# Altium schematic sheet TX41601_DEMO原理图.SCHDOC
size A3
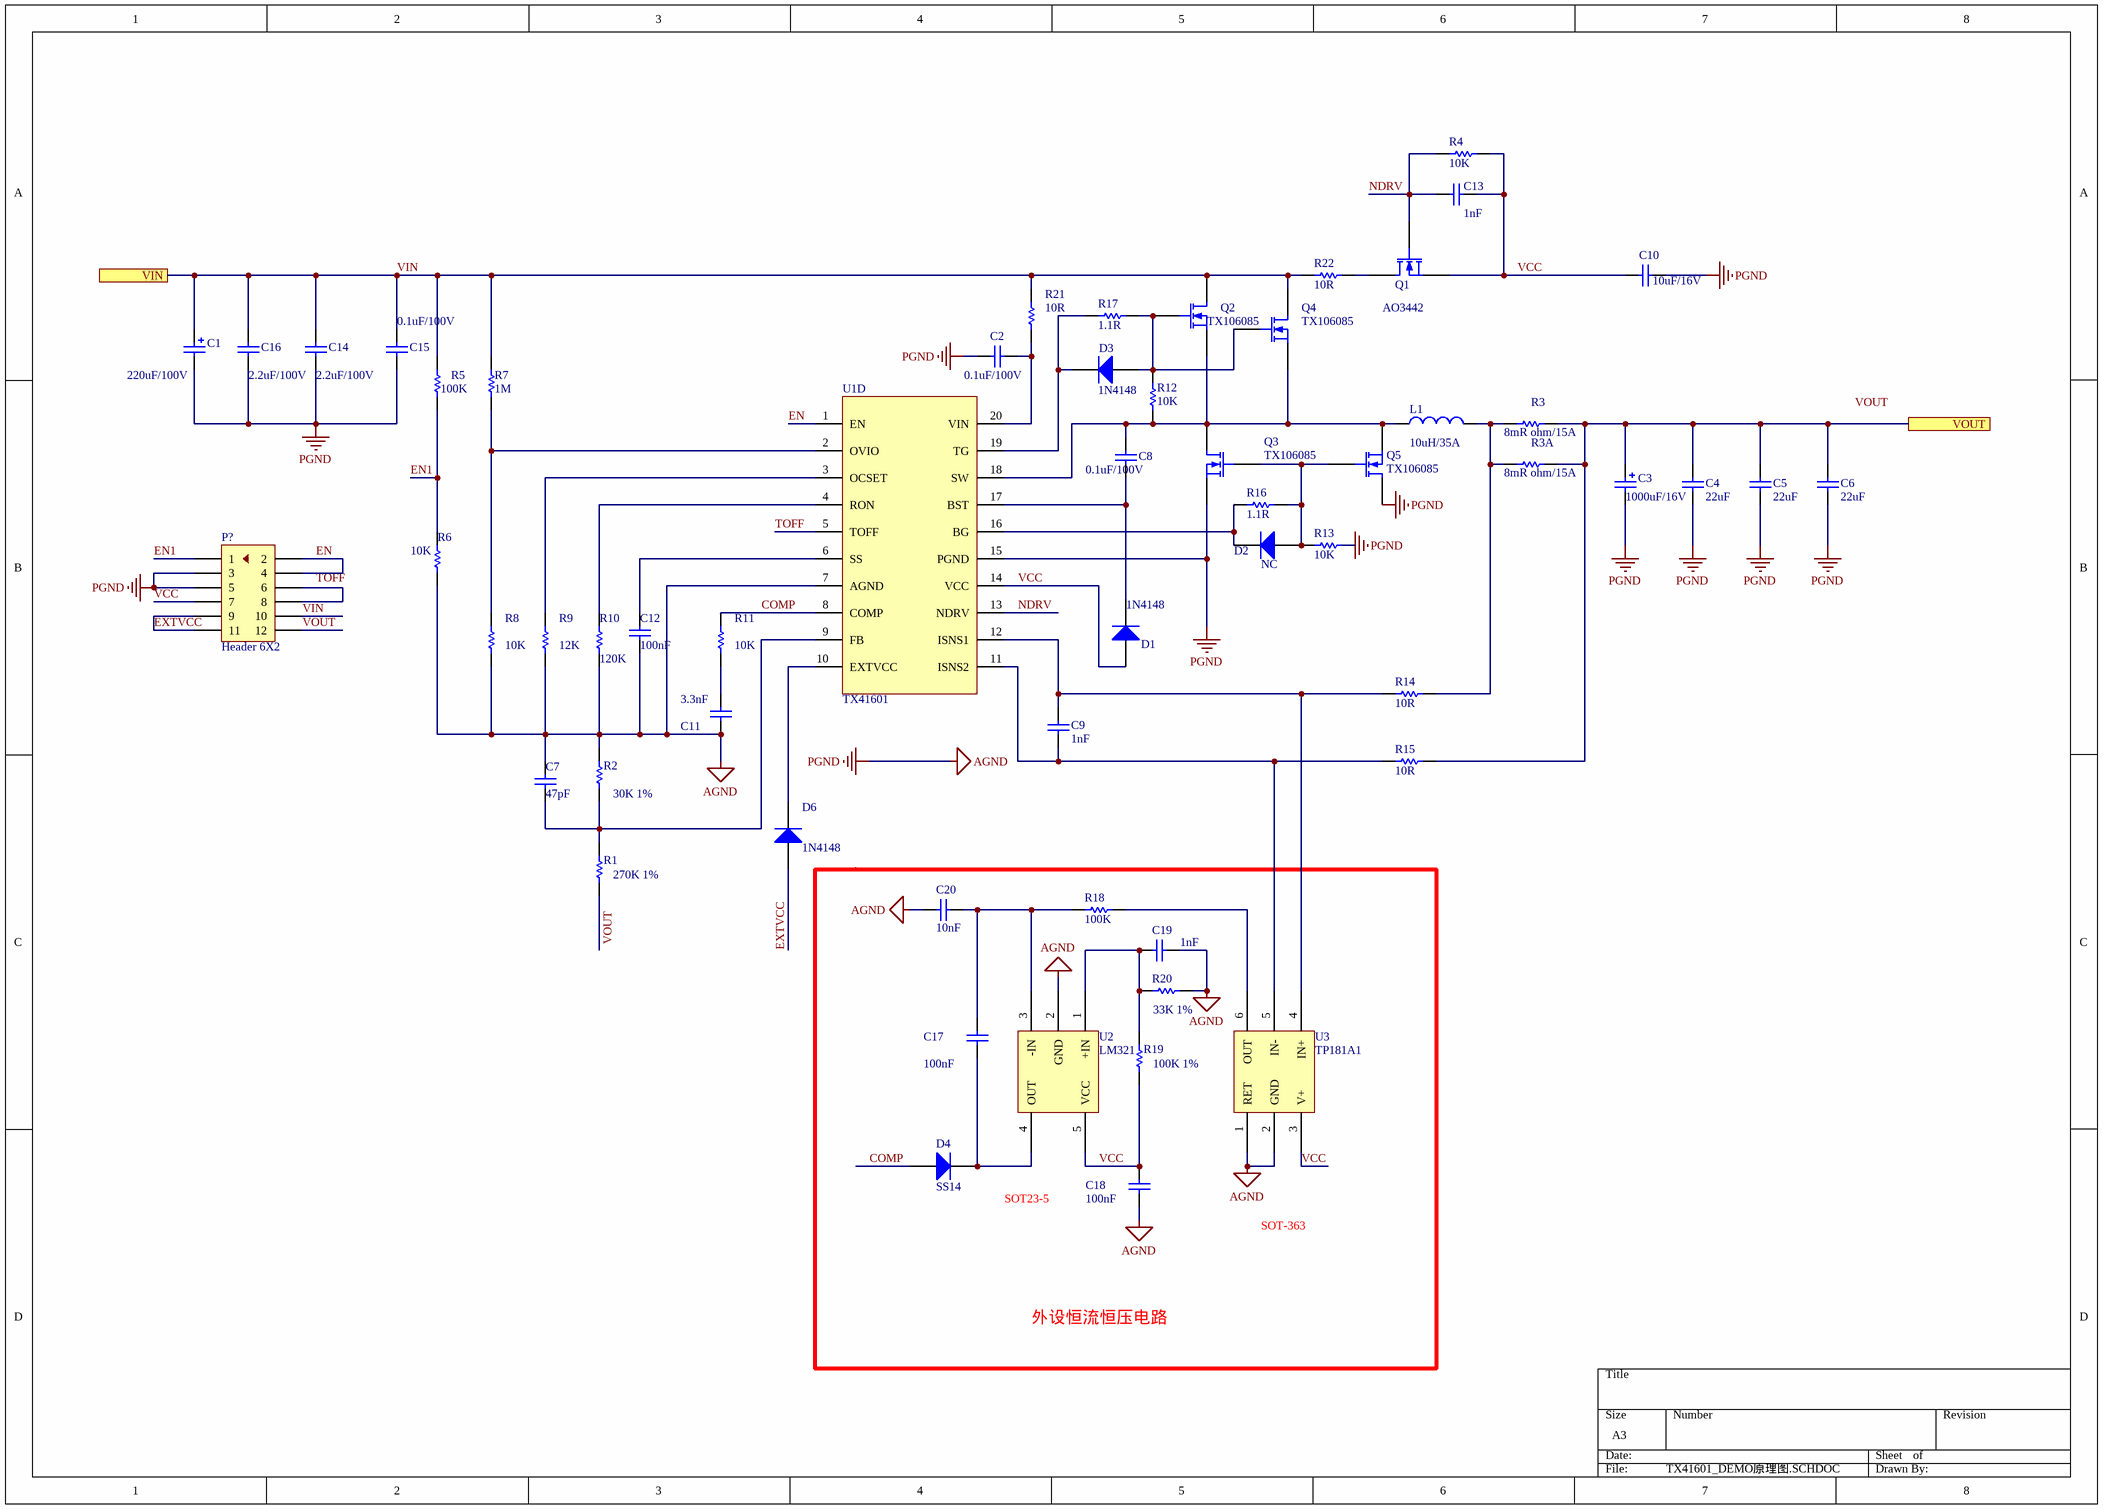
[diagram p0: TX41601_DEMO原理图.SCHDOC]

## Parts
C1  value 220uF/100V  [C13]  (hidden comment: Cap Pol1)
C2  value 0.1uF/100V  [0805]  (hidden comment: Cap Semi)
C3  value 1000uF/16V  [C8]  (hidden comment: Cap Pol1)
C4  value 22uF  [1206]  (hidden comment: Cap Semi)
C5  value 22uF  [1206]  (hidden comment: Cap Semi)
C6  value 22uF  [1206]  (hidden comment: Cap Semi)
C7  value 47pF  [0603]  (hidden comment: Cap Semi)
C8  value 0.1uF/100V  [0603]  (hidden comment: Cap Semi)
C9  value 1nF  [0603]  (hidden comment: Cap Semi)
C10  value 10uF/16V  [0603]  (hidden comment: Cap Semi)
C11  value 3.3nF  [0603]  (hidden comment: Cap Semi)
C12  value 100nF  [0603]  (hidden comment: Cap Semi)
C13  value 1nF  [0603]  (hidden comment: Cap Semi)
C14  value 2.2uF/100V  [1812]  (hidden comment: Cap Semi)
C15  value 0.1uF/100V  [0805]  (hidden comment: Cap Semi)
C16  value 2.2uF/100V  [1812]  (hidden comment: Cap Semi)
C17  value 100nF  [0603]  (hidden comment: Cap Semi)
C18  value 100nF  [0603]  (hidden comment: Cap Semi)
C19  value 1nF  [0603]  (hidden comment: Cap Semi)
C20  value 10nF  [0603]  (hidden comment: Cap Semi)
D1  SubClass: 1N4148  [SMA]  (hidden comment: Diode)
D2  NC  [SMA]
D3  1N4148  [SMA]
D4  SS14  [SMA]
D6  1N4148  [SMA]
L1  10uH/35A  [LIN12]
P?  Header 6X2  [HDR5X2-2.54]
Q1  AO3442  [TO252 - duplicate]
Q2  TX106085  [TO252 - duplicate]
Q3  TX106085  [TO252 - duplicate]
Q4  TX106085  [TO252 - duplicate]
Q5  TX106085  [TO252 - duplicate]
R1  value 30K 1%  [0603]  (hidden comment: Res Semi)
R2  value 270K 1%  [0603]  (hidden comment: Res Semi)
R3  value 8mR ohm/15A  [1812]  (hidden comment: Res Semi)
R3A  value 8mR ohm/15A  [1812]  (hidden comment: Res Semi)
R4  value 10K  [0603]  (hidden comment: Res Semi)
R5  value 100K  [0603]  (hidden comment: Res Semi)
R6  value 10K  [0603]  (hidden comment: Res Semi)
R7  value 1M  [0603]  (hidden comment: Res Semi)
R8  value 10K  [0603]  (hidden comment: Res Semi)
R9  value 12K  [0603]  (hidden comment: Res Semi)
R10  value 120K  [0603]  (hidden comment: Res Semi)
R11  value 10K  [0603]  (hidden comment: Res Semi)
R12  value 10K  [0603]  (hidden comment: Res Semi)
R13  value 10K  [0603]  (hidden comment: Res Semi)
R14  value 10R  [0603]  (hidden comment: Res Semi)
R15  value 10R  [0603]  (hidden comment: Res Semi)
R16  value 1.1R  [0603]  (hidden comment: Res Semi)
R17  value 1.1R  [0603]  (hidden comment: Res Semi)
R18  value 100K  [0603]  (hidden comment: Res Semi)
R19  value 100K 1%  [0603]  (hidden comment: Res Semi)
R20  value 33K 1%  [0603]  (hidden comment: Res Semi)
R21  value 10R  [0603]  (hidden comment: Res Semi)
R22  value 10R  [0603]  (hidden comment: Res Semi)
U1  TX41601  (part D of 4)
U2  LM321
U3  TP181A1

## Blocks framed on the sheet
外设恒流恒压电路: C17-C20 D4 R18-R20 U2 U3

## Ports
VIN, VOUT

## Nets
AGND: C1.2 C2.2 C3.2 C4.1 C5.1 C6.1 C7.2 C10.1 C11.2 C12.1 C14.2 C15.2 C16.2 C18.2 C19.2 C20.1 P?.3 P?.5 Q3.3(S) Q5.1(D) R2.1 R6.1 R8.1 R9.2 R10.2 R13.2 R20.2 U1.7(AGND) U1.15(PGND) U2.2(GND) U3.1(RET) U3.2(GND)  [also labelled PGND]
COMP: D4.1(A) R11.1 U1.8(COMP)
EN: P?.2 P?.4 U1.1(EN)
EN1: P?.1 R5.1 R6.2
EXTVCC: D6.1(A) P?.9 P?.10(11)
NDRV: C13.2 Q1.2(G) R4.2 U1.13(NDRV)
TOFF: U1.5(TOFF)
VCC: C10.2 C13.1 C18.1 D1.1(A) P?.7 Q1.3(S) R4.1 R19.1 U1.14(VCC) U2.5(VCC) U3.3(V+)
VIN: C1.1 C14.1 C15.1 C16.1 P?.10 Q2.1(D) Q4.1(D) R5.2 R7.2 R21.2 R22.1 ; port VIN
VOUT: P?.10(12) R1.1
VOUT: C3.1 C4.2 C5.2 C6.2 R3.2 R3A.2 R15.2 ; port VOUT  [a separate net that carries the same name]
NetC2_1: C2.1 R21.1 U1.20(VIN)
NetC7_1: C7.1 R1.2 R2.2 U1.9(FB)
NetC8_1: C8.1 D1.2(K) U1.17(BST)
NetC8_2: C8.2 L1.1 Q2.3(S) Q3.1(D) Q4.3(S) Q5.3(S) R12.1 U1.18(SW)
NetC9_1: C9.1 R15.1 U1.11(ISNS2) U3.5(IN-)
NetC9_2: C9.2 R14.1 U1.12(ISNS1) U3.4(IN+)
NetC11_1: C11.1 R11.2
NetC12_2: C12.2 U1.6(SS)
NetC17_1: C17.1 C20.2 R18.1 U2.3(-IN)
NetC17_2: C17.2 D4.2(K) U2.4(OUT)
NetC19_1: C19.1 R19.2 R20.1 U2.1(+IN)
NetD2_1: D2.1(A) Q3.2(G) Q5.2(G) R13.1 R16.2
NetD2_2: D2.2(K) R16.1 U1.16(BG)
NetD3_1: D3.1(A) Q2.2(G) Q4.2(G) R12.2 R17.2
NetD3_2: D3.2(K) R17.1 U1.19(TG)
NetD6_2: D6.2(K) U1.10(EXTVCC)
NetL1_2: L1.2 R3.1 R3A.1 R14.2
NetP?_6: P?.6 P?.8
NetQ1_1: Q1.1(D) R22.2
NetR7_1: R7.1 R8.2 U1.2(OVIO)
NetR9_1: R9.1 U1.3(OCSET)
NetR10_1: R10.1 U1.4(RON)
NetR18_2: R18.2 U3.6(OUT)

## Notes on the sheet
- SOT23-5
- SOT-363
- Labels drawn without touching a wire or pin: TOFF, VOUT

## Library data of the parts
C1 C3 = Cap Pol1: Polarized Capacitor (Radial); Manufacturer: Generic Components; Class: Passive
C2 C4-C20 = Cap Semi: Capacitor (Semiconductor SIM Model); Manufacturer: Generic Components; Class: Passive
D1-D4 D6 = Diode: Default Diode; Manufacturer: Generic Components; Class: Discrete
L1 = Inductor: Manufacturer: Generic Components; Class: Passive; Value: 10mH
P? = Header 5X2: 接插件
Q1-Q5 = MOSFET-N: N-Channel MOSFET; Manufacturer: Generic Components; Class: Discrete; SubClass: MOSFET - Low Power
R1-R3 R3A R4-R22 = Res Semi: Semiconductor Resistor; Manufacturer: Generic Components; Class: Passive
